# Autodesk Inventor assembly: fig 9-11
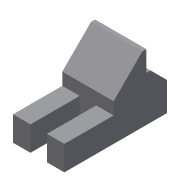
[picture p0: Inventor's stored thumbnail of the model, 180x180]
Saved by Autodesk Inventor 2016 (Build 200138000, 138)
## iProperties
Shininess: 64.0
Length Units: 11269
Angle Units: 11279
Time Units: 11290
Mass Units: 11283
Length Display Precision: 3
Angle Display Precision: 2
Created: 2002-01
Part Number: fig 9-11
Document SubType Name: Assembly
Designer: ***
Density: 0.0
Volumn: 0.0
Area: 0.0
PropertySet Name: Model Information
Control State: 0
Master: False
Checked Out: False
Author: ***
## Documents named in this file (3)
- D:\KAVITA\Autodesk Inventor_ 2016 Project_Kavita\Inventor_Part Files\Inventor_2016_Part\c09_Inv_2016\c09_inv_2016_prt\fig 9-11.iam
- D:\KAVITA\Autodesk Inventor_ 2016 Project_Kavita\Inventor_Part Files\Inventor_2016_Part\c09_Inv_2016\c09_inv_2016_prt\Part3.ipt
- D:\KAVITA\Autodesk Inventor_ 2016 Project_Kavita\Inventor_Part Files\Inventor_2016_Part\c09_Inv_2016\c09_inv_2016_prt\Part4.ipt
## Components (2 placed, 2 different names)
1. Part3:1 — Mate:1
2. Part4:1 — Mate:1
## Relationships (1: Mate 1)
- Mate:1: Part3:1 ↔ Part4:1
